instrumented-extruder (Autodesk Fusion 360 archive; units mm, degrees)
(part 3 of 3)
sketch "Sketch2" plane through (0, -11, 0) normal (0, -1, 0) x axis (1, 0, 0)
  line L1 (0, -5) -> (0, 80)
  line L2 (67, -5) -> (0, -5)
  line L3 (67, 80) -> (67, -5)
  line L4 (0, 80) -> (67, 80)
  line L5 (5, 66) -> (5, 49)
  line L6 (35, 66) -> (5, 66)
  line L7 (60, 66) -> (35, 66)
  line L8 (5, 25.5) -> (5, 13)
  line L9 (48.5, 25.5) -> (5, 25.5)
  line L10 (48.5, 1) -> (48.5, 25.5)
  circle C1 centre (5, 49) radius 1.35
  circle C2 centre (35, 66) radius 1.35
  circle C3 centre (60, 66) radius 1.35
  circle C4 centre (60, 66) radius 2.75
  circle C5 centre (35, 66) radius 2.75
  circle C6 centre (5, 49) radius 2.75
  circle C7 centre (5, 13) radius 1.35
  circle C8 centre (48.5, 25.5) radius 1.35
  circle C9 centre (48.5, 1) radius 1.35
  circle C10 centre (5, 13) radius 2.75
  circle C11 centre (48.5, 25.5) radius 2.75
  circle C12 centre (48.5, 1) radius 2.75
  point P6 (5, 49)
  point P10 (5, 49)
  point P8 (35, 66)
  point P11 (35, 66)
  point P9 (60, 66)
  point P12 (60, 66)
  point P20 (5, 13)
  point P23 (5, 13)
  point P16 (5, 13)
  point P18 (48.5, 25.5)
  point P21 (48.5, 25.5)
  point P24 (48.5, 25.5)
  point P19 (48.5, 1)
  point P22 (48.5, 1)
  point P25 (48.5, 1)
  point P7 (5, 66)
  point P2 (0, 80)
  point P15 (5, 49)
  point P17 (5, 25.5)
  point P3 (0, -5)
  vertical L5
  perpendicular L5 L6
  parallel L6 L7
  coincident P6 P10
  coincident P8 P11
  coincident P9 P12
  concentric C3 C4
  concentric C2 C5
  concentric C1 C6
  equal C1 C2
  equal C2 C3
  equal C4 C5
  equal C4 C6
  vertical L8
  perpendicular L8 L9
  perpendicular L9 L10
  equal C11 C12
  equal C10 C11
  equal C6 C10
  equal C8 C9
  equal C7 C8
  equal C1 C7
  coincident P20 P23
  coincident P16 P23
  coincident P18 P21
  coincident P21 P24
  coincident P19 P22
  coincident P22 P25
  dimension "d11" distance P6 P7 = 17
  dimension "d12" distance P7 P8 = 30
  dimension "d13" distance P8 P9 = 25
  dimension "d14" diameter C1 = 2.7
  dimension "d15" diameter C6 = 5.5
  dimension "d16" distance P2 L5 = 5
  dimension "d17" distance P2 P15 = 31
  dimension "d27" distance P18 P19 = 24.5
  dimension "d28" distance P17 P18 = 43.5
  dimension "d29" distance P16 P17 = 12.5
  dimension "d30" distance P2 P23 = 5
  dimension "d31" distance P3 P20 = 18
extrude "Extrude3" cut sketch "Sketch2" profile of C1 C2 C3 C7 C8 C9 to an object offset 1
extrude "Extrude4" add sketch "Sketch2" profile of C1 C2 C3 C4 C5 C6 along normal blind 3
chamfer "Chamfer1" distance 3
joint "Assemble1" alignAngle 0 alignOffsetX 0 alignOffsetY 0 alignOffsetZ 0
extrude "Extrude5" add sketch "Sketch2" profile of C7 C8 C9 C10 C11 C12 along normal blind 10
chamfer "Chamfer2" distance 8 distance 10
joint "Assemble2" alignAngle 0 alignOffsetX 0 alignOffsetY 0 alignOffsetZ 0
sketch "Sketch3" plane through (11, 0, 0) normal (1, 0, 0) x axis (0, 1, 0)
  line L1 (3.5, -5) -> (-6, -5)
  line L2 (3.5, 80) -> (3.5, -5)
  line L3 (-6, 80) -> (3.5, 80)
  line L4 (-6, -5) -> (-6, 80)
  line L5 (-6, 40) -> (3.5, 40)
  circle C1 centre (0, 0) radius 2.75
  circle C2 centre (0, 50) radius 2.75
  point P8 (3.5, 40)
  point P9 (-6, 40)
  point P3 (0, 50)
  coincident L2 P8
  coincident L4 P9
  perpendicular L4 L5
  dimension "d41" distance P3 L5 = 10
extrude "Extrude6" add sketch "Sketch3" profile of C2 L2 L3 L4 L5 along normal blind 12
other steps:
joint_origin "JointOrigin1"
joint_origin "JointOrigin2"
